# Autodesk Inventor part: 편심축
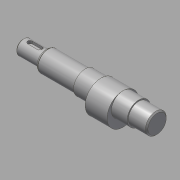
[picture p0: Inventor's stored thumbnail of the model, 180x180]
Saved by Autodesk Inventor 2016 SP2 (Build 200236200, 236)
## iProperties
Created: 2017-08
Part Number: 편심축
Material: 강철, 연강
Document SubType Name: Modeling
Designer: mduedu
Density: 1 g/cm^3
Appearance: 강철
Author: mduedu
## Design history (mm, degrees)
sketch "스케치1"
  geometry: L1 (0, 0)-(110, 0); L2 (110, 0)-(110, 8.5); L3 (110, 8.5)-(95, 8.5); L4 (95, 8.5)-(95, 9.5); L5 (95, 9.5)-(51, 9.5); L6 (51, 9.5)-(51, 8.5); L7 (51, 8.5)-(19, 8.5); L8 (19, 8.5)-(19, 6); L9 (19, 6)-(0, 6); L10 (0, 6)-(0, 0)
  constraints: 20 end point, 6 parallel, 2 collinear, 2 perpendicular, 1 horizontal
  dimensions: "d0" = 110 distance of L1.start L1.end; "d1" = 17 diameter of L3 L1; "d2" = 19 diameter of L5 L1; "d3" = 12 diameter of L9 L1; "d4" = 19 distance of L8.end L9.end; "d5" = 15 distance of L2.end L3.end; "d6" = 44 distance of L4.end L5.end
revolve "회전1" sketch "스케치1" stored, may be unused: angle "d7" = 90 deg
node "작업 평면1"
sketch "스케치2"
  geometry: C1 r 9.5 at (0, 0) reference; C2 r 13 at (0, -3.5); 1 further point
  constraints: 1 centre point, 1 tangent, 1 vertical alignment
  dimensions: "d8" = 3.5 distance of point (0, 0) C2.centre
extrude "돌출1" join sketch "스케치2" stored distance "d9" = 18; taper "d10" = 0 deg
chamfer "모따기1" distance "d11" = 1; stored, may be unused: second distance "d12" = 2, angle "d13" = 45 deg
node "작업 평면2"
sketch "스케치3"
  geometry: L1 (3.5, -2)-(-4.5, -2); L2 (-4.5, -2)-(-4.5, 2); L3 (-4.5, 2)-(3.5, 2); L4 (3.5, 2)-(3.5, -2); L5 (9.5, 6)-(9.5, -6) reference; A1 r 2 centre (3.5, 0) between (3.5, -2) and (3.5, 2); A2 r 2 centre (-4.5, 0) between (-4.5, 2) and (-4.5, -2); A3 r 2 centre (3.5, 0) between (3.5, 2) and (3.5, -2); A4 r 2 centre (-4.5, 0) between (-4.5, -2) and (-4.5, 2); 1 further point
  constraints: 8 end point, 8 point on circle, 4 centre point, 2 midpoint, 2 parallel, 1 horizontal, 1 horizontal alignment, 1 perpendicular
  dimensions: "d14" = 12 dimension on A2 A1; "d16" = 4 distance between parallel lines of L3 L1; "d17" = 4 distance edge to line of A1 L5
extrude "돌출2" cut sketch "스케치3" distance "d18" = 2.5; taper "d19" = 0 deg
chamfer "모따기2" distance "d20" = 1; stored, may be unused: second distance "d21" = 2, angle "d22" = 45 deg
chamfer "모따기3" distance "d23" = 1; stored, may be unused: second distance "d24" = 2, angle "d25" = 60 deg
fillet "모깎기1" dims "d26" = 0.5
hole "구멍1" diameter "d29" = 3.242; stored, may be unused: countersink angle "d33" = 90 deg, drill point angle "d35" = 118 deg; dims "d30" = 8, "d31" = 4, "d32" = 2, "d34" = 10, "d36" = 10, "d37" = 10
node "솔리드1"
node "절단 모서리 투영1"
